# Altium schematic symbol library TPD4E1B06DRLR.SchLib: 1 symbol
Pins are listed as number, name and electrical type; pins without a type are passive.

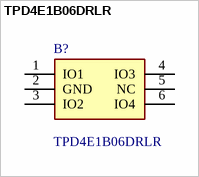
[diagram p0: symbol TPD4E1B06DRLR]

## TPD4E1B06DRLR
designator B?
Bidirectional Quad-Channel High-Speed ESD Protection Device; Manufacturer_Name: Texas Instruments; Geometry.Height: 0.6mm
footprint SOTFL50P160X60-6N
pins: 1 IO1, 2 GND, 3 IO2, 4 IO3, 5 NC, 6 IO4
